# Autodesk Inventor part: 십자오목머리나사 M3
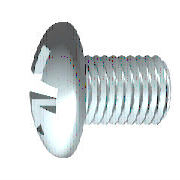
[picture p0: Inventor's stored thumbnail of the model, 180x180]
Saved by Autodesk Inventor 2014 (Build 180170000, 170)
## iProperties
Created: 2012-02
Part Number: 십자오목머리나사 M3
Material: 강철, 연강
Description: 십자 오목 머리 나사
Document SubType Name: Modeling
Standard: KS B 1023
Designer: mduedu
Standards Organization: KS
Language: ko-KR
Size Designation: A  M 3 x 6 - H
Categories: <MemberInstance><Categories><Category DisplayName="조임쇠" InternalName="e4da775c-781d-43d5-af7c-5136215cf5a6" Mnemonic="FSTN"><Category DisplayName="볼트" InternalN
Density: 7.86 g/cm^3
Appearance: 강철
Mass: 0.662382 g
Surface Area: 1.40192 cm^2
Volume: 0.0842726 cm^3
IsCustomPart: 0
Author: mduedu
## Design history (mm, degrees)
workplane "Work Plane3"
sketch "스케치2"
  geometry: L1 (-3.72, 0)-(3.72, 0) reference; L2 (0, -3.72)-(0, 3.72) reference; L3 (0, 1.5)-(0, 0); L4 (0, 0)-(1.5, 0); L5 (0, 0)-(1.879, 1.879); L6 (0.253, 1.479)-(0.261, 0.456); L7 (1.479, 0.253)-(0.456, 0.261); L8 (0.253, -1.479)-(0.261, -0.456); L9 (1.479, -0.253)-(0.456, -0.261); L10 (-0.253, 1.479)-(-0.261, 0.456); L11 (-1.479, 0.253)-(-0.456, 0.261); L12 (-1.479, -0.253)-(-0.456, -0.261); L13 (-0.253, -1.479)-(-0.261, -0.456); A1 r 0.45 centre (0, 0) between (0.45, 0) and (0, 0.45); A2 r 1.5 centre (0, 0) between (1.5, 0) and (1.479, 0.253); A3 r 1.5 centre (0, 0) between (0.253, 1.479) and (0, 1.5); A4 r 1.5 centre (0, 0) between (1.479, 0.253) and (0.253, 1.479); A5 r 1.5 centre (0, 0) between (0, -1.5) and (0.253, -1.479); A6 r 1.5 centre (0, 0) between (0.253, -1.479) and (1.479, -0.253); A7 r 1.5 centre (0, 0) between (1.479, -0.253) and (1.5, 0); A8 r 1.5 centre (0, 0) between (-1.479, 0.253) and (-1.5, 0); A9 r 1.5 centre (0, 0) between (-0.253, 1.479) and (-1.479, 0.253); A10 r 1.5 centre (0, 0) between (0, 1.5) and (-0.253, 1.479); A11 r 1.5 centre (0, 0) between (-1.5, 0) and (-1.479, -0.253); A12 r 1.5 centre (0, 0) between (-1.479, -0.253) and (-0.253, -1.479); A13 r 1.5 centre (0, 0) between (-0.253, -1.479) and (0, -1.5); A14 r 0.525 centre (0, 0) between (0.525, 0) and (0, 0.525); A15 r 0.197 centre (0.457, 0.457) between (0.261, 0.456) and (0.456, 0.261); A16 r 0.197 centre (0.457, -0.457) between (0.456, -0.261) and (0.261, -0.456); A17 r 0.197 centre (-0.457, 0.457) between (-0.456, 0.261) and (-0.261, 0.456); A18 r 0.197 centre (-0.457, -0.457) between (-0.261, -0.456) and (-0.456, -0.261); 1 further point
  constraints: 38 point on circle, 22 end point, 19 symmetric about line, 18 centre point, 4 coincident, 3 collinear, 3 point on line, 3 tangent, 1 perpendicular, 21 other
  dimensions: "d4" = 45 deg angle of L5 L4; "d5" = 0.9 diameter of A1 (= 0.3 x SDM); "d6" = 3 diameter of A4 (= SDM); "d7" = 0.2525 distance from line of L6.start L3 (= 0.5 x SBR); "d14" = 1.05 diameter of A14 (= 0.35 x SDM)
extrude "슬롯" join sketch "스케치2" taper "d15" = 5 deg; stored distance "d54" = 10
revolve "절단부" stored, may be unused: angle "d56" = 90 deg
revolve "본체" stored, may be unused: angle "d18" = 90 deg
workplane "Work Plane1"
body "Solid1"
sketch "스케치1"
  geometry: L1 (6, 0)-(6, 1.5); L2 (6, 1.5)-(1, 1.5); L3 (3.962, 5.08)-(3.962, 5.08); L4 (-2.4, 0)-(-2.4, 2.59); L5 (-2.2, 1.4)-(-1.036, 0.82); L6 (-1.036, 0.82)-(-0.6, 0); L7 (-0.6, 0)-(6, 0); L8 (-4.305, 0)-(7.717, 0) reference; L9 (0, -1.016)-(0, 6.096) reference; L10 (-2.2, 1.4)-(-2.4, 1.5); L11 (-1.636, 2.657)-(-2.4, 2.59); L12 (-1.636, 2.657)-(0, 2.8); L13 (0, 2.8)-(0, 1.347); L14 (0, 1.347)-(0.693, 1.347); L15 (0.693, 1.347)-(1, 1.5); L16 (1, 1.5)-(0, 1.5); A1 r 5 centre (2.6, 0) between (-1.636, 2.657) and (-2.4, 0)
  constraints: 28 end point, 5 point on line, 4 collinear, 4 point on circle, 3 parallel, 2 perpendicular, 1 centre point, 1 horizontal, 1 tangent
  dimensions: "d1" = 3 diameter of L2 L7 (= GD); "d2" = 1.8 distance from line of L6.end L4 (= STI); "d11" = 3 diameter of L10.end L7 (= SDM); "d12" = 62 deg angle of L6 L7; "d13" = 26.5 deg angle of L5 L7; "d17" = 5.6 diameter of L12.end L7 (= KOD); "d19" = 5 deg angle of L12 L7 (= KEWI); "d20" = 2.4 distance between parallel lines of L4 L13 (= KOH); "d21" = 5 radius of A1 (= KR); "d23" = 2.6935 diameter of L14 L7 (= BDM); "d24" = 5 distance of L1.end L2.end (= GEL); "d25" = 0.30673 horizontal distance of L14.end L2.end (= GAL); "d28" = 6 distance between parallel lines of L1 L13 (= NLG)
fillet "모깎기1" dims "d29" = 1.2 (= RR)
fillet "모깎기2" dims "d16" = 0.101 (= 0.2 x SBR)
feature "스레드" dims "d8" = 5 (= GEL), "d9" = 0
chamfer "모따기1" distance "d26" = 0.30673 (= -0.5 x SPD + 0.5 x GD); stored, may be unused: second distance "d27" = 0.30683 (computed from GUL), angle "d78" = 45 deg
other parameters: "GD" = 3 (= NND) [user parameter; used in 2 equation terms], "NLG" = 6 [user parameter; used in 1 equation term], "GEL" = 5 [user parameter; used in 2 equation terms], "KOD" = 5.6 [user parameter; used in 1 equation term], "KOH" = 2.4 [user parameter; used in 2 equation terms], "SDM" = 3 [user parameter; used in 4 equation terms], "STI" = 1.8 [user parameter; used in 1 equation term], "SBR" = 0.505 [user parameter; used in 2 equation terms], "GAL" = 0.30673 (= 0.61345 x PTC) [user parameter; used in 1 equation term], "SPD" = 2.38655 (= NND - 1.2269 x PTC) [user parameter; used in 1 equation term], "KEWI" = 5 deg [user parameter; used in 1 equation term], "d3" = -2.4 (= -KOH), "d10" = 0, "KR" = 5 [user parameter; used in 1 equation term], "BDM" = 2.6935 [user parameter; used in 1 equation term], "GUL" = 0.30673 (= 0.61345 x PTC) [user parameter; used in 1 equation term], "RR" = 1.2 [user parameter; used in 1 equation term], "d79" = 0, "d80" = 0, "PTC" = 0.5 [user parameter; used in 5 equation terms], "THREADDIA" = 3 [user parameter; used in 1 equation term], "TOA" = 30 deg [user parameter], "NND" = 3 [user parameter; used in 2 equation terms], "GD1" = 2.38655 (= THREADDIA - 1.2269 x PTC) [user parameter]
